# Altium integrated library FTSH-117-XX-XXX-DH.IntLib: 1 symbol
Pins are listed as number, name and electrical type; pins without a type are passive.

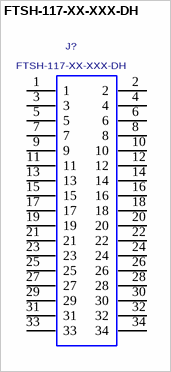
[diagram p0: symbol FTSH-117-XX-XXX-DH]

## FTSH-117-XX-XXX-DH
designator J?
.050 X .050 C.L. DOUBLE HORIZONTAL TERMINAL STRIP; MANUFACTURER: SAMTEC
footprint FTSH-117-XX-XXX-DH
pins: 1, 2, 3, 4, 5, 6, 7, 8, 9, 10, 11, 12, 13, 14, 15, 16, 17, 18, 19, 20, 21, 22, 23, 24, 25, 26, 27, 28, 29, 30, 31, 32, 33, 34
